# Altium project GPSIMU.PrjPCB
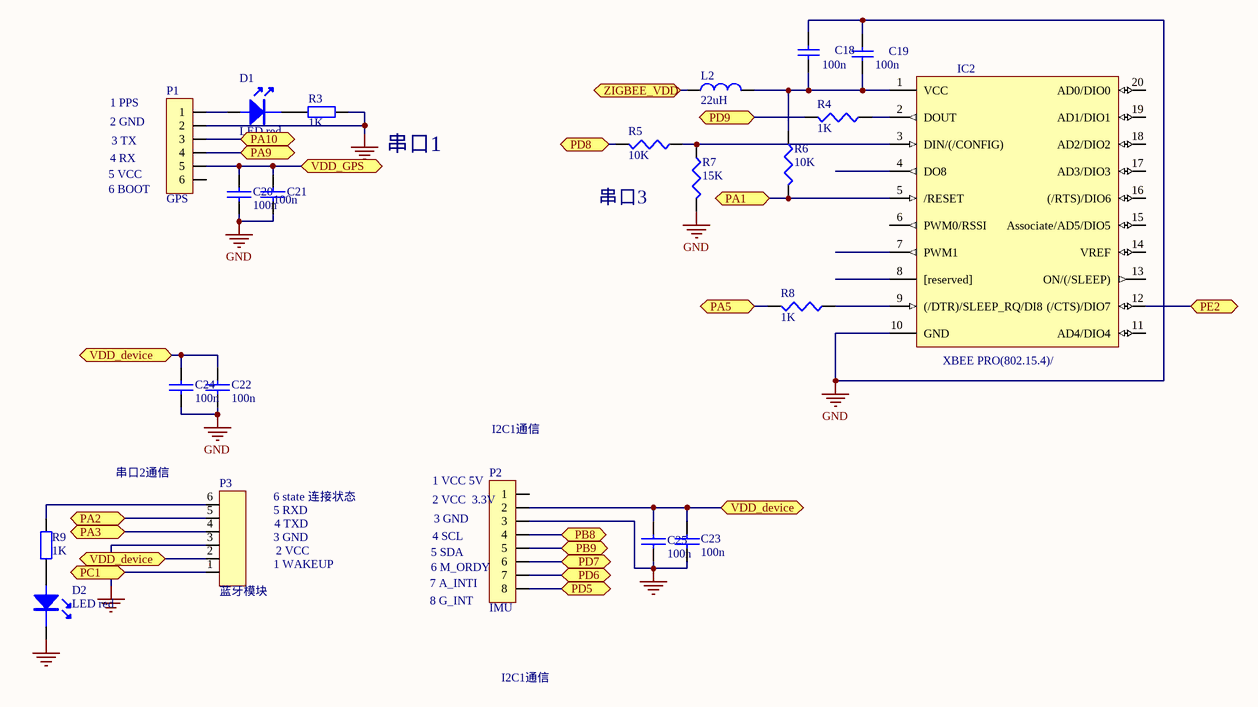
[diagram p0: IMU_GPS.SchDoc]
5 sheets, 107 parts. Net scope: flat (ports and power ports of the same name join across sheets).
Board file: GPSIMU(G).PcbDoc
Sheets:
  IMU_GPS.SchDoc
  IMU_REIO.SchDoc
  CPU_STM32F4.SchDoc
  IMU_POW.SchDoc
  IMU_SD.SchDoc

## Sheet IMU_GPS.SchDoc
size A3

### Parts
C18  100n  [0603]
C19  100n  [0603]
C20  100n  [0603]
C21  100n  [0603]
C22  100n  [0603]
C23  100n  [0603]
C24  100n  [0603]
C25  100n  [0603]
D1  LED red  [D0805]
D2  LED red  [D0805]
IC2  XBEE PRO(802.15.4)/  [SMT-Zigbee-2.0]
L2  22uH  [0603]
P1  GPS  [GPS 28*28MM]
P2  IMU  [GY-85]
P3  蓝牙模块  [HC-06(35.7*15.2MM)]
R3  1K  [0603]
R4  1K  [0603]
R5  10K  [0603]
R6  10K  [0603]
R7  15K  [0603]
R8  1K  [0603]
R9  1K  [0603]

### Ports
PA1, PA2, PA3, PA5, PA9, PA10, PB8, PB9, PC1, PD5, PD6, PD7, PD8, PD9, PE2, VDD_device, VDD_GPS, ZIGBEE_VDD

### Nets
GND: C18.2 C19.2 C20.1 C21.1 C22.1 C23.1 C24.1 C25.1 D2.K IC2.10(GND) P1.2 P2.3 P3.3 R3.1 R7.2
VDD_device: C22.2 C23.2 C24.2 C25.2 P2.2 P3.2 ; port VDD_device
VDD_GPS: C20.2 C21.2 P1.5 ; port VDD_GPS
ZIGBEE_VDD: L2.1 ; port ZIGBEE_VDD
PA1: IC2.5(/RESET) R6.2 ; port PA1
PA2: P3.5 ; port PA2
PA3: P3.4 ; port PA3
PA5: R8.2 ; port PA5
PA9: P1.4 ; port PA9
PA10: P1.3 ; port PA10
PB8: P2.4 ; port PB8
PB9: P2.5 ; port PB9
PC1: P3.1 ; port PC1
PD5: P2.8 ; port PD5
PD6: P2.7 ; port PD6
PD7: P2.6 ; port PD7
PD8: R5.2 ; port PD8
PD9: R4.2 ; port PD9
PE2: IC2.12((/CTS)/DIO7) ; port PE2
NetC18_1: C18.1 C19.1 IC2.1(VCC) L2.2 R6.1
NetD1_A: D1.A P1.1
NetD1_K: D1.K R3.2
NetD2_A: D2.A R9.1
NetIC2_2: IC2.2(DOUT) R4.1
NetIC2_3: IC2.3(DIN/(/CONFIG)) R5.1 R7.1
NetIC2_9: IC2.9((/DTR)/SLEEP_RQ/DI8) R8.1
NetP3_6: P3.6 R9.2

Not connected (* = marked no-connect by the designer): IC2 4(DO8) 6(PWM0/RSSI) 7(PWM1) 8([reserved]) 11(AD4/DIO4) 13(ON/(/SLEEP)) 14(VREF) 15(Associate/AD5/DIO5) 16((/RTS)/DIO6) 17(AD3/DIO3) 18(AD2/DIO2) 19(AD1/DIO1) 20(AD0/DIO0); P1 6; P2 1

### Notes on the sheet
- (near P1) 1 PPS
- (near P1) 2 GND
- (near P1) 6 BOOT
- 5 VCC
- 4 RX
- 3 TX
- 串口1
- (near R5) 串口3
- I2C1通信
- 串口2通信
- 6 state 连接状态
- 5 RXD
- 4 TXD
- (near P2) 1 VCC 5V
- (near P2) 2 VCC  3.3V
- (near P2) 3 GND
- 1 WAKEUP
- 3 GND
- 2 VCC
- (near P2) 7 A_INTI
- (near P2) 6 M_ORDY
- 5 SDA
- (near P2) 4 SCL
- (near P2) 8 G_INT

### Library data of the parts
C18 = Cap: Capacitor
C19 = Cap: Capacitor; Value: 1u
C20-C25 = C-SMD
D1 D2 = diode-LED: LED
IC2 = XBEE PRO(802.15.4)
L2 = L-: Value: 10mH
P1 = CON6-2.54: (栅)围栏式立(卧)6PIN
P2 = CON8-2.54: (栅)围栏式立(卧)8PIN
P3 = CON-SIP6-2.54: 单排针6PIN
R3 R9 = R-0603: 0603(SMD); 功率: 1/10w
R4 R8 = Res3: Resistor; Value: 10K
R5-R7 = Res3: Resistor

## Sheet IMU_REIO.SchDoc
size A4
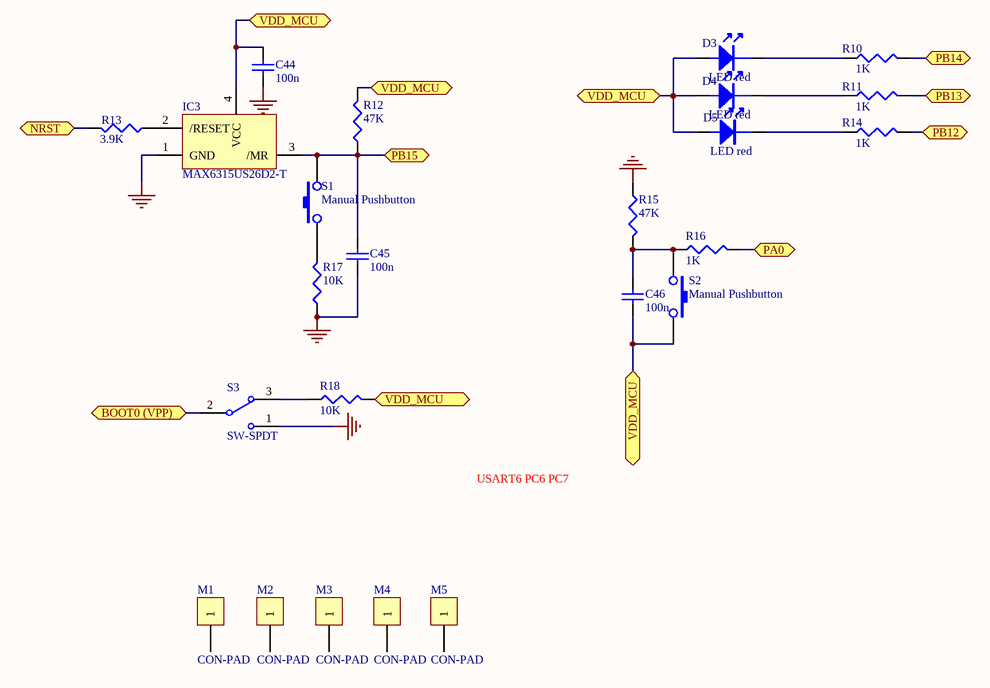
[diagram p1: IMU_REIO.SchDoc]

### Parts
C44  100n  [0603]
C45  100n  [0603]
C46  100n  [0603]
D3  LED red  [D0805]
D4  LED red  [D0805]
D5  LED red  [D0805]
IC3  MAX6315US26D2-T  [TO-253]
M1  CON-PAD  [BAD_MARK]
M2  CON-PAD  [BAD_MARK]
M3  CON-PAD  [BAD_MARK]
M4  CON-PAD  [BAD_MARK]
M5  CON-PAD  [BAD_MARK]
R10  1K  [0603]
R11  1K  [0603]
R12  47K  [0603]
R13  3.9K  [0603]
R14  1K  [0603]
R15  47K  [0603]
R16  1K  [0603]
R17  10K  [0603]
R18  10K  [0603]
S1  Manual Pushbutton  [KEY-6*4]
S2  Manual Pushbutton  [KEY-6*4]
S3  SW-SPDT  [SW-PD-5(10)]

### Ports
BOOT0 (VPP), NRST, PA0, PB12, PB13, PB14, PB15, VDD_MCU

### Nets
GND: C44.2 C45.2 IC3.1(GND) R15.1 R17.1 S3.1
VBAT: C44.1 C46.2 D3.A D4.A D5.A IC3.4(VCC) R12.2 R18.2 S2.2 ; port VDD_MCU
BOOT0 (VPP): S3.2 ; port BOOT0 (VPP)
NRST: R13.2 ; port NRST
PA0: R16.2 ; port PA0
PB12: R14.2 ; port PB12
PB13: R11.2 ; port PB13
PB14: R10.2 ; port PB14
PB15: C45.1 IC3.3(/MR) R12.1 S1.2 ; port PB15
NetC46_1: C46.1 R15.2 R16.1 S2.1
NetD3_K: D3.K R10.1
NetD4_K: D4.K R11.1
NetD5_K: D5.K R14.1
NetIC3_2: IC3.2(/RESET) R13.1
NetR17_2: R17.2 S1.1
NetR18_1: R18.1 S3.3

Not connected (* = marked no-connect by the designer): M1 1; M2 1; M3 1; M4 1; M5 1

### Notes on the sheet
- USART6 PC6 PC7

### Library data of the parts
C44-C46 = Cap: TANTAMOUNT? 595D Vishay Sprague,50V,22.5mOhm
D3-D5 = diode-LED: LED
IC3 = MAX 6468: MAX 6468XS16D3 Reset and Supervisory Circuit
R10-R18 = Res3: Resistor
S1 S2 = 微动开关
S3 = SW-SPDT: SPDT Subminiature Toggle Switch, Right Angle Mounting, Vertical Actuation

## Sheet CPU_STM32F4.SchDoc
size A2
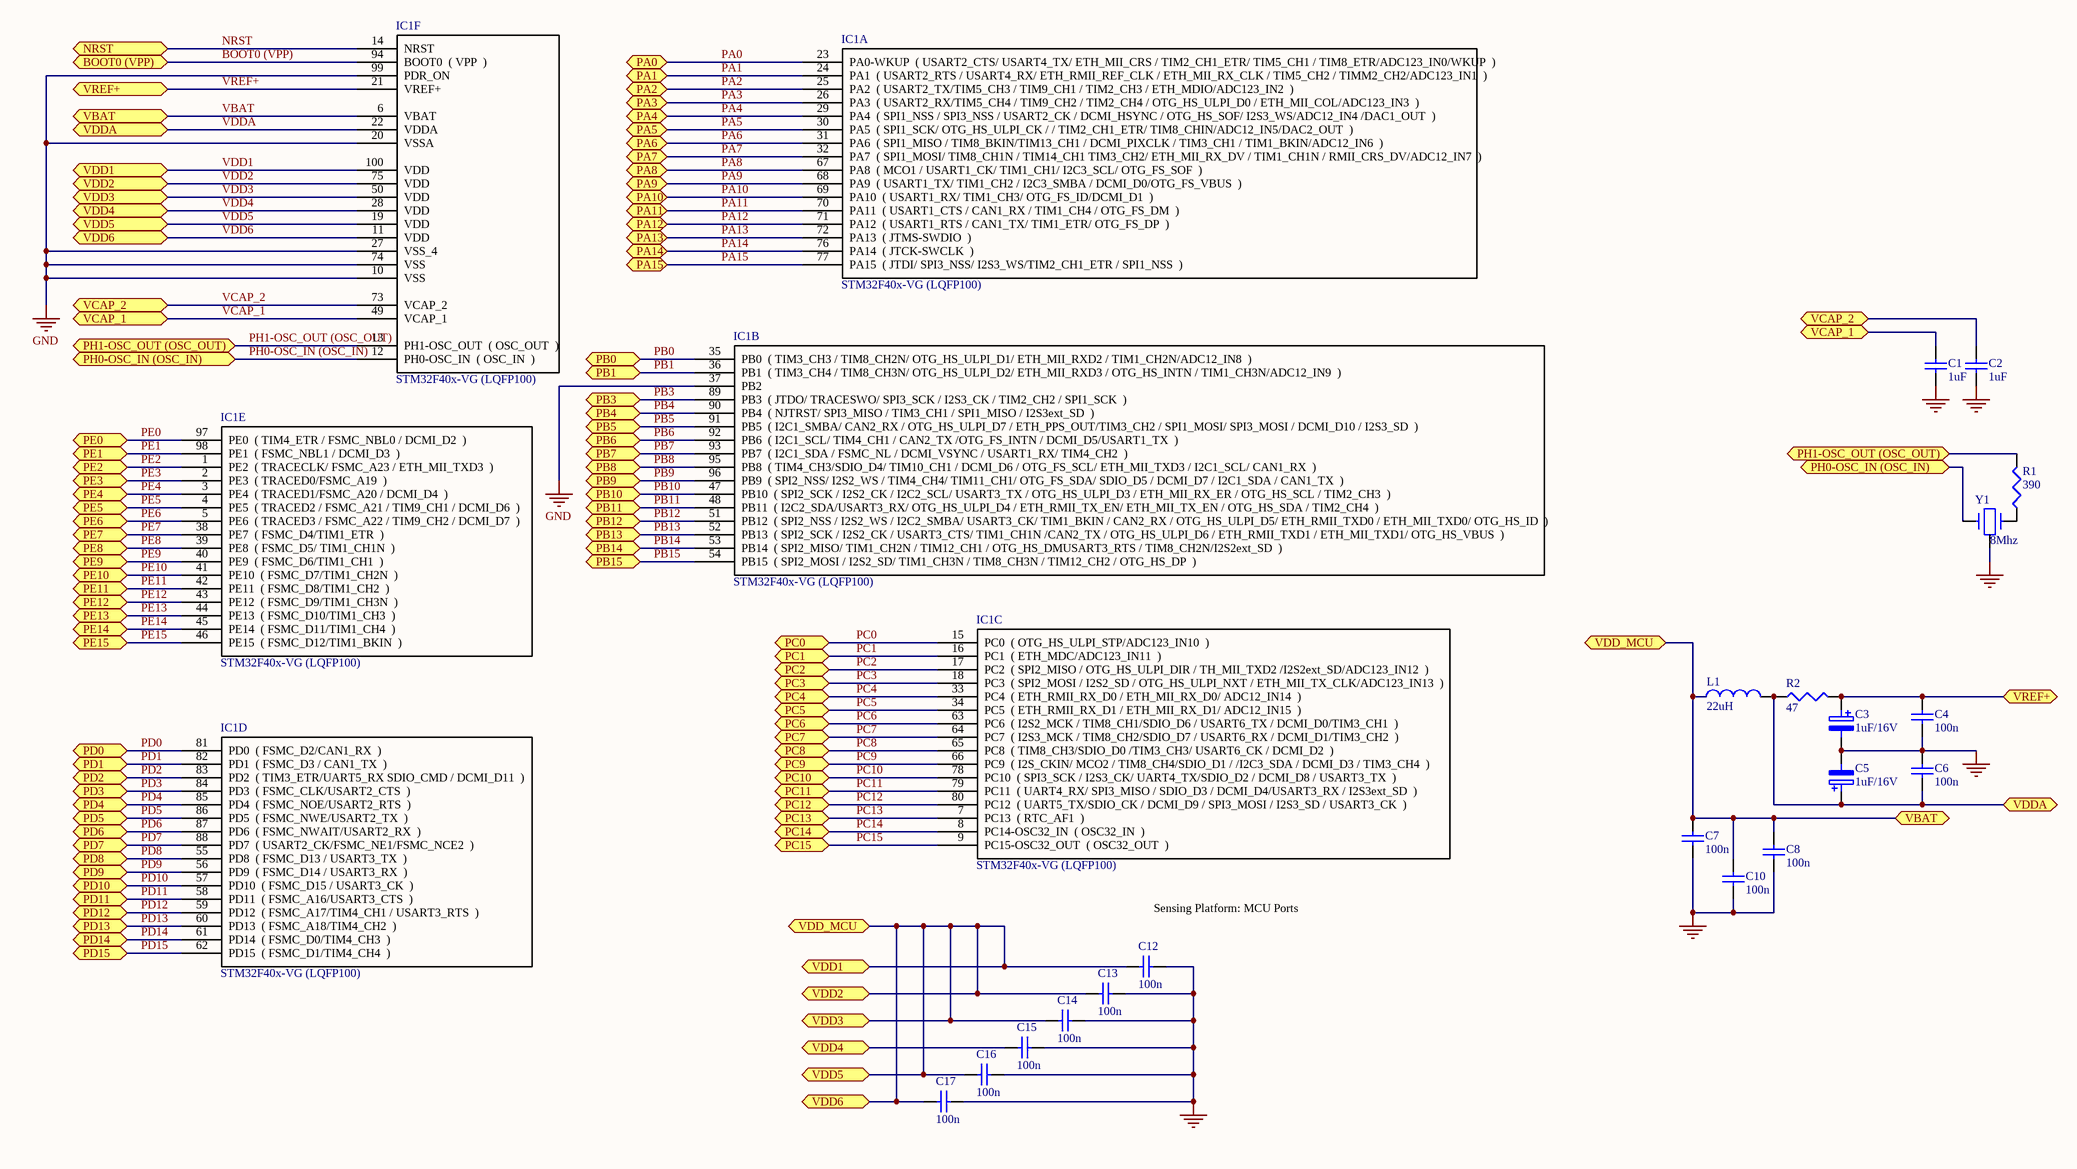
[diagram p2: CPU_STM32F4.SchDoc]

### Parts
C1  1uF  [0603]
C2  1uF  [0603]
C3  1uF/16V  [C-M(0805)]
C4  100n  [0603]
C5  1uF/16V  [C-M(0805)]
C6  100n  [0603]
C7  100n  [0603]
C8  100n  [0603]
C10  100n  [0603]
C12  100n  [0603]
C13  100n  [0603]
C14  100n  [0603]
C15  100n  [0603]
C16  100n  [0603]
C17  100n  [0603]
IC1  STM32F40x-VG (LQFP100)  [LQFP100 (14*14)]  (parts A,B,C,D,E,F of 6)
L1  22uH  [0603]
R1  390  [0603]
R2  47  [0603]
Y1  8Mhz  [XT-3.2*1.5]

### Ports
BOOT0 (VPP), NRST, PA0, PA1, PA2, PA3, PA4, PA5, PA6, PA7, PA8, PA9, PA10, PA11, PA12, PA13, PA14, PA15, PB0, PB1, PB3, PB4, PB5, PB6, PB7, PB8, PB9, PB10, PB11, PB12, PB13, PB14, PB15, PC0, PC1, PC2, PC3, PC4, PC5, PC6, PC7, PC8, PC9, PC10, PC11, PC12, PC13, PC14, PC15, PD0, PD1, PD2, PD3, PD4, PD5, PD6, PD7, PD8, PD9, PD10, PD11, PD12, PD13, PD14, PD15, PE0, PE1, PE2, PE3, PE4, PE5, PE6, PE7, PE8, PE9, PE10, PE11, PE12, PE13, PE14, PE15, PH0-OSC_IN (OSC_IN), PH1-OSC_OUT (OSC_OUT), VBAT, VCAP_1, VCAP_2, VDD1, VDD2, VDD3, VDD4, VDD5, VDD6, VDD_MCU, VDDA, VREF+

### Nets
GND: C1.1 C2.1 C3.2 C4.1 C5.2 C6.2 C7.1 C8.1 C10.1 C12.2 C13.2 C14.2 C15.2 C16.2 C17.2 IC1.10(VSS) IC1.20(VSSA) IC1.27(VSS_4) IC1.37(PB2) IC1.74(VSS) IC1.99(PDR_ON) Y1.2
VBAT: C7.2 C8.2 C10.2 C12.1 C13.1 C14.1 C16.1 C17.1 IC1.6(VBAT) IC1.11(VDD) IC1.19(VDD) IC1.50(VDD) IC1.75(VDD) IC1.100(VDD) L1.1 ; port VBAT, port VDD1, port VDD2, port VDD3, port VDD5, port VDD6, port VDD_MCU  [also labelled VDD1, VDD2, VDD3, VDD5, VDD6]
BOOT0 (VPP): IC1.94(BOOT0__(_VPP__)) ; port BOOT0 (VPP)
NRST: IC1.14(NRST) ; port NRST
PA0: IC1.23(PA0-WKUP__(_USART2_CTS/_USART4_TX/_ETH_MII_CRS_/_TIM2_CH1_ETR/_TIM5_CH1_/_TIM8_ETR/ADC123_IN0/WKUP__)) ; port PA0
PA1: IC1.24(PA1__(_USART2_RTS_/_USART4_RX/_ETH_RMII_REF_CLK_/_ETH_MII_RX_CLK_/_TIM5_CH2_/_TIMM2_CH2/ADC123_IN1__)) ; port PA1
PA2: IC1.25(PA2__(_USART2_TX/TIM5_CH3_/_TIM9_CH1_/_TIM2_CH3_/_ETH_MDIO/ADC123_IN2__)) ; port PA2
PA3: IC1.26(PA3__(_USART2_RX/TIM5_CH4_/_TIM9_CH2_/_TIM2_CH4_/_OTG_HS_ULPI_D0_/_ETH_MII_COL/ADC123_IN3__)) ; port PA3
PA4: IC1.29(PA4__(_SPI1_NSS_/_SPI3_NSS_/_USART2_CK_/_DCMI_HSYNC_/_OTG_HS_SOF/_I2S3_WS/ADC12_IN4_/DAC1_OUT__)) ; port PA4
PA5: IC1.30(PA5__(_SPI1_SCK/_OTG_HS_ULPI_CK_/_/_TIM2_CH1_ETR/_TIM8_CHIN/ADC12_IN5/DAC2_OUT__)) ; port PA5
PA6: IC1.31(PA6__(_SPI1_MISO_/_TIM8_BKIN/TIM13_CH1_/_DCMI_PIXCLK_/_TIM3_CH1_/_TIM1_BKIN/ADC12_IN6__)) ; port PA6
PA7: IC1.32(PA7__(_SPI1_MOSI/_TIM8_CH1N_/_TIM14_CH1_TIM3_CH2/_ETH_MII_RX_DV_/_TIM1_CH1N_/_RMII_CRS_DV/ADC12_IN7__)) ; port PA7
PA8: IC1.67(PA8__(_MCO1_/_USART1_CK/_TIM1_CH1/_I2C3_SCL/_OTG_FS_SOF__)) ; port PA8
PA9: IC1.68(PA9__(_USART1_TX/_TIM1_CH2_/_I2C3_SMBA_/_DCMI_D0/OTG_FS_VBUS__)) ; port PA9
PA10: IC1.69(PA10__(_USART1_RX/_TIM1_CH3/_OTG_FS_ID/DCMI_D1__)) ; port PA10
PA11: IC1.70(PA11__(_USART1_CTS_/_CAN1_RX_/_TIM1_CH4_/_OTG_FS_DM__)) ; port PA11
PA12: IC1.71(PA12__(_USART1_RTS_/_CAN1_TX/_TIM1_ETR/_OTG_FS_DP__)) ; port PA12
PA13: IC1.72(PA13__(_JTMS-SWDIO__)) ; port PA13
PA14: IC1.76(PA14__(_JTCK-SWCLK__)) ; port PA14
PA15: IC1.77(PA15__(_JTDI/_SPI3_NSS/_I2S3_WS/TIM2_CH1_ETR_/_SPI1_NSS__)) ; port PA15
PB0: IC1.35(PB0__(_TIM3_CH3_/_TIM8_CH2N/_OTG_HS_ULPI_D1/_ETH_MII_RXD2_/_TIM1_CH2N/ADC12_IN8__)) ; port PB0
PB1: IC1.36(PB1__(_TIM3_CH4_/_TIM8_CH3N/_OTG_HS_ULPI_D2/_ETH_MII_RXD3_/_OTG_HS_INTN_/_TIM1_CH3N/ADC12_IN9__)) ; port PB1
PB3: IC1.89(PB3__(_JTDO/_TRACESWO/_SPI3_SCK_/_I2S3_CK_/_TIM2_CH2_/_SPI1_SCK__)) ; port PB3
PB4: IC1.90(PB4__(_NJTRST/_SPI3_MISO_/_TIM3_CH1_/_SPI1_MISO_/_I2S3ext_SD__)) ; port PB4
PB5: IC1.91(PB5__(_I2C1_SMBA/_CAN2_RX_/_OTG_HS_ULPI_D7_/_ETH_PPS_OUT/TIM3_CH2_/_SPI1_MOSI/_SPI3_MOSI_/_DCMI_D10_/_I2S3_SD__)) ; port PB5
PB6: IC1.92(PB6__(_I2C1_SCL/_TIM4_CH1_/_CAN2_TX_/OTG_FS_INTN_/_DCMI_D5/USART1_TX__)) ; port PB6
PB7: IC1.93(PB7__(_I2C1_SDA_/_FSMC_NL_/_DCMI_VSYNC_/_USART1_RX/_TIM4_CH2__)) ; port PB7
PB8: IC1.95(PB8__(_TIM4_CH3/SDIO_D4/_TIM10_CH1_/_DCMI_D6_/_OTG_FS_SCL/_ETH_MII_TXD3_/_I2C1_SCL/_CAN1_RX__)) ; port PB8
PB9: IC1.96(PB9__(_SPI2_NSS/_I2S2_WS_/_TIM4_CH4/_TIM11_CH1/_OTG_FS_SDA/_SDIO_D5_/_DCMI_D7_/_I2C1_SDA_/_CAN1_TX__)) ; port PB9
PB10: IC1.47(PB10__(_SPI2_SCK_/_I2S2_CK_/_I2C2_SCL/_USART3_TX_/_OTG_HS_ULPI_D3_/_ETH_MII_RX_ER_/_OTG_HS_SCL_/_TIM2_CH3__)) ; port PB10
PB11: IC1.48(PB11__(_I2C2_SDA/USART3_RX/_OTG_HS_ULPI_D4_/_ETH_RMII_TX_EN/_ETH_MII_TX_EN_/_OTG_HS_SDA_/_TIM2_CH4__)) ; port PB11
PB12: IC1.51(PB12__(_SPI2_NSS_/_I2S2_WS_/_I2C2_SMBA/_USART3_CK/_TIM1_BKIN_/_CAN2_RX_/_OTG_HS_ULPI_D5/_ETH_RMII_TXD0_/_ETH_MII_TXD0/_OTG_HS_ID__)) ; port PB12
PB13: IC1.52(PB13__(_SPI2_SCK_/_I2S2_CK_/_USART3_CTS/_TIM1_CH1N_/CAN2_TX_/_OTG_HS_ULPI_D6_/_ETH_RMII_TXD1_/_ETH_MII_TXD1/_OTG_HS_VBUS__)) ; port PB13
PB14: IC1.53(PB14__(_SPI2_MISO/_TIM1_CH2N_/_TIM12_CH1_/_OTG_HS_DMUSART3_RTS_/_TIM8_CH2N/I2S2ext_SD__)) ; port PB14
PB15: IC1.54(PB15__(_SPI2_MOSI_/_I2S2_SD/_TIM1_CH3N_/_TIM8_CH3N_/_TIM12_CH2_/_OTG_HS_DP__)) ; port PB15
PC0: IC1.15(PC0__(_OTG_HS_ULPI_STP/ADC123_IN10__)) ; port PC0
PC1: IC1.16(PC1__(_ETH_MDC/ADC123_IN11__)) ; port PC1
PC2: IC1.17(PC2__(_SPI2_MISO_/_OTG_HS_ULPI_DIR_/_TH_MII_TXD2_/I2S2ext_SD/ADC123_IN12__)) ; port PC2
PC3: IC1.18(PC3__(_SPI2_MOSI_/_I2S2_SD_/_OTG_HS_ULPI_NXT_/_ETH_MII_TX_CLK/ADC123_IN13__)) ; port PC3
PC4: IC1.33(PC4__(_ETH_RMII_RX_D0_/_ETH_MII_RX_D0/_ADC12_IN14__)) ; port PC4
PC5: IC1.34(PC5__(_ETH_RMII_RX_D1_/_ETH_MII_RX_D1/_ADC12_IN15__)) ; port PC5
PC6: IC1.63(PC6__(_I2S2_MCK_/_TIM8_CH1/SDIO_D6_/_USART6_TX_/_DCMI_D0/TIM3_CH1__)) ; port PC6
PC7: IC1.64(PC7__(_I2S3_MCK_/_TIM8_CH2/SDIO_D7_/_USART6_RX_/_DCMI_D1/TIM3_CH2__)) ; port PC7
PC8: IC1.65(PC8__(_TIM8_CH3/SDIO_D0_/TIM3_CH3/_USART6_CK_/_DCMI_D2__)) ; port PC8
PC9: IC1.66(PC9__(_I2S_CKIN/_MCO2_/_TIM8_CH4/SDIO_D1_/_/I2C3_SDA_/_DCMI_D3_/_TIM3_CH4__)) ; port PC9
PC10: IC1.78(PC10__(_SPI3_SCK_/_I2S3_CK/_UART4_TX/SDIO_D2_/_DCMI_D8_/_USART3_TX__)) ; port PC10
PC11: IC1.79(PC11__(_UART4_RX/_SPI3_MISO_/_SDIO_D3_/_DCMI_D4/USART3_RX_/_I2S3ext_SD__)) ; port PC11
PC12: IC1.80(PC12__(_UART5_TX/SDIO_CK_/_DCMI_D9_/_SPI3_MOSI_/_I2S3_SD_/_USART3_CK__)) ; port PC12
PC13: IC1.7(PC13__(_RTC_AF1__)) ; port PC13
PC14: IC1.8(PC14-OSC32_IN__(_OSC32_IN__)) ; port PC14
PC15: IC1.9(PC15-OSC32_OUT__(_OSC32_OUT__)) ; port PC15
PD0: IC1.81(PD0__(_FSMC_D2/CAN1_RX__)) ; port PD0
PD1: IC1.82(PD1__(_FSMC_D3_/_CAN1_TX__)) ; port PD1
PD2: IC1.83(PD2__(_TIM3_ETR/UART5_RX_SDIO_CMD_/_DCMI_D11__)) ; port PD2
PD3: IC1.84(PD3__(_FSMC_CLK/USART2_CTS__)) ; port PD3
PD4: IC1.85(PD4__(_FSMC_NOE/USART2_RTS__)) ; port PD4
PD5: IC1.86(PD5__(_FSMC_NWE/USART2_TX__)) ; port PD5
PD6: IC1.87(PD6__(_FSMC_NWAIT/USART2_RX__)) ; port PD6
PD7: IC1.88(PD7__(_USART2_CK/FSMC_NE1/FSMC_NCE2__)) ; port PD7
PD8: IC1.55(PD8__(_FSMC_D13_/_USART3_TX__)) ; port PD8
PD9: IC1.56(PD9__(_FSMC_D14_/_USART3_RX__)) ; port PD9
PD10: IC1.57(PD10__(_FSMC_D15_/_USART3_CK__)) ; port PD10
PD11: IC1.58(PD11__(_FSMC_A16/USART3_CTS__)) ; port PD11
PD12: IC1.59(PD12__(_FSMC_A17/TIM4_CH1_/_USART3_RTS__)) ; port PD12
PD13: IC1.60(PD13__(_FSMC_A18/TIM4_CH2__)) ; port PD13
PD14: IC1.61(PD14__(_FSMC_D0/TIM4_CH3__)) ; port PD14
PD15: IC1.62(PD15__(_FSMC_D1/TIM4_CH4__)) ; port PD15
PE0: IC1.97(PE0__(_TIM4_ETR_/_FSMC_NBL0_/_DCMI_D2__)) ; port PE0
PE1: IC1.98(PE1__(_FSMC_NBL1_/_DCMI_D3__)) ; port PE1
PE2: IC1.1(PE2__(_TRACECLK/_FSMC_A23_/_ETH_MII_TXD3__)) ; port PE2
PE3: IC1.2(PE3__(_TRACED0/FSMC_A19__)) ; port PE3
PE4: IC1.3(PE4__(_TRACED1/FSMC_A20_/_DCMI_D4__)) ; port PE4
PE5: IC1.4(PE5__(_TRACED2_/_FSMC_A21_/_TIM9_CH1_/_DCMI_D6__)) ; port PE5
PE6: IC1.5(PE6__(_TRACED3_/_FSMC_A22_/_TIM9_CH2_/_DCMI_D7__)) ; port PE6
PE7: IC1.38(PE7__(_FSMC_D4/TIM1_ETR__)) ; port PE7
PE8: IC1.39(PE8__(_FSMC_D5/_TIM1_CH1N__)) ; port PE8
PE9: IC1.40(PE9__(_FSMC_D6/TIM1_CH1__)) ; port PE9
PE10: IC1.41(PE10__(_FSMC_D7/TIM1_CH2N__)) ; port PE10
PE11: IC1.42(PE11__(_FSMC_D8/TIM1_CH2__)) ; port PE11
PE12: IC1.43(PE12__(_FSMC_D9/TIM1_CH3N__)) ; port PE12
PE13: IC1.44(PE13__(_FSMC_D10/TIM1_CH3__)) ; port PE13
PE14: IC1.45(PE14__(_FSMC_D11/TIM1_CH4__)) ; port PE14
PE15: IC1.46(PE15__(_FSMC_D12/TIM1_BKIN__)) ; port PE15
PH0-OSC_IN (OSC_IN): IC1.12(PH0-OSC_IN__(_OSC_IN__)) Y1.1 ; port PH0-OSC_IN (OSC_IN)
PH1-OSC_OUT (OSC_OUT): IC1.13(PH1-OSC_OUT__(_OSC_OUT__)) R1.2 ; port PH1-OSC_OUT (OSC_OUT)
VCAP_1: C1.2 IC1.49(VCAP_1) ; port VCAP_1
VCAP_2: C2.2 IC1.73(VCAP_2) ; port VCAP_2
VDD4: C15.1 IC1.28(VDD) ; port VDD4
VDDA: C5.1 C6.1 IC1.22(VDDA) L1.2 R2.1 ; port VDDA
VREF+: C3.1 C4.2 IC1.21(VREF+) R2.2 ; port VREF+
NetR1_1: R1.1 Y1.3

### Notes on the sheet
- (near C12) Sensing Platform: MCU Ports

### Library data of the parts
C1 C2 = Cap: TANTAMOUNT? 595D Vishay Sprague,50V,22.5mOhm; Value: 1u
C3 C5 = C-A(3216-18): 耐压: 10V
C4 C6-C8 C10 C13-C17 = Cap: as C44 on sheet IMU_REIO
C12 = Cap: TANTAMOUNT? 595D Vishay Sprague,50V,22.5mOhm; Value: 4.7u
IC1 = STM32F40x-VG
L1 = Inductor: fcm1608-0603; Code_IEC: 1005
R1 R2 = Res3: Resistor
Y1 = CRYSTAL-X3: 3PIN; 频率: 20MHZ-39.9MHZ

## Sheet IMU_POW.SchDoc
size A3
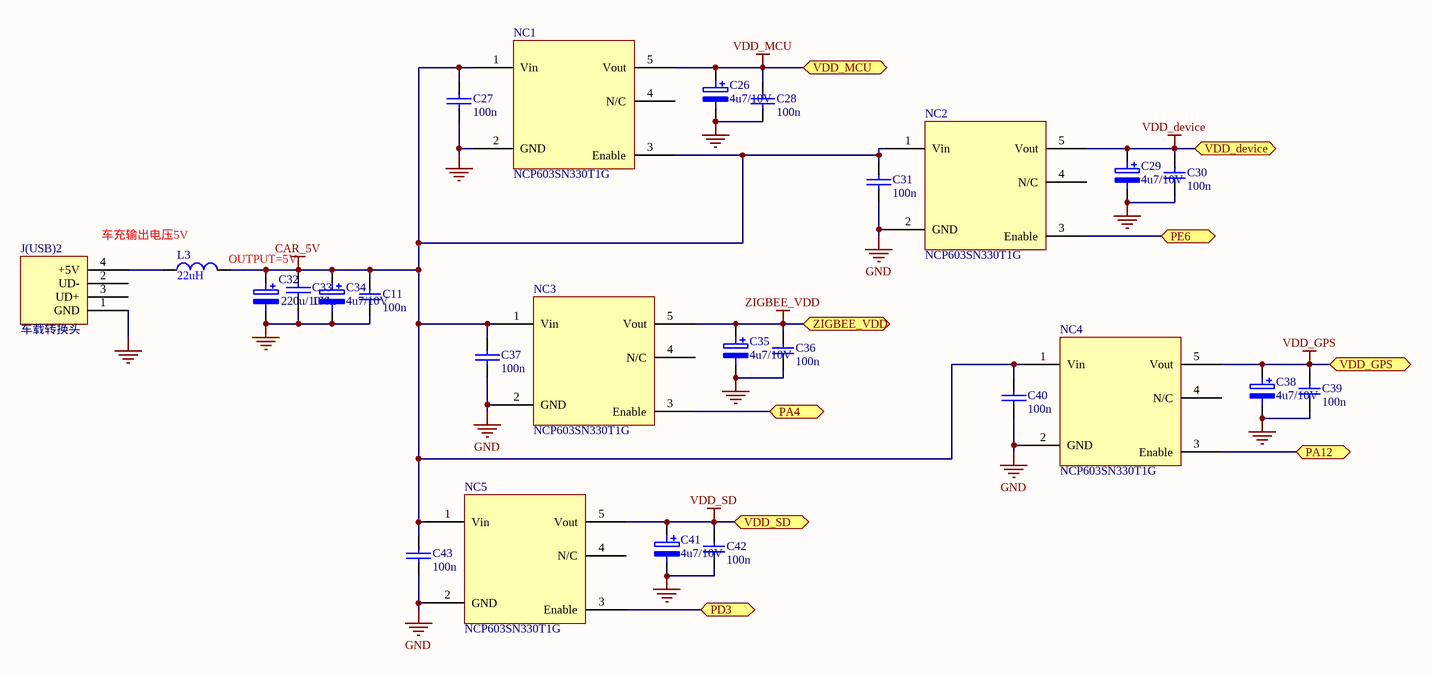
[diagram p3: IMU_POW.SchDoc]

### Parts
C11  100n  [0603]
C26  4u7/10V  [C-A(3216-18)]
C27  100n  [0603]
C28  100n  [0603]
C29  4u7/10V  [C-A(3216-18)]
C30  100n  [0603]
C31  100n  [0603]
C32  220u/10V  [C-C(6032-28)]
C33  100n  [0603]
C34  4u7/10V  [C-A(3216-18)]
C35  4u7/10V  [C-A(3216-18)]
C36  100n  [0603]
C37  100n  [0603]
C38  4u7/10V  [C-A(3216-18)]
C39  100n  [0603]
C40  100n  [0603]
C41  4u7/10V  [C-A(3216-18)]
C42  100n  [0603]
C43  100n  [0603]
J(USB)2  车载转换头  [SMT-USB]
L3  22uH  [0603]
NC1  NCP603SN330T1G  [TSSOP-5]
NC2  NCP603SN330T1G  [TSSOP-5]
NC3  NCP603SN330T1G  [TSSOP-5]
NC4  NCP603SN330T1G  [TSSOP-5]
NC5  NCP603SN330T1G  [TSSOP-5]

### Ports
PA4, PA12, PD3, PE6, VDD_device, VDD_GPS, VDD_MCU, VDD_SD, ZIGBEE_VDD

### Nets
CAR_5V: C11.2 C27.2 C31.2 C32.1 C33.2 C34.1 C37.2 C40.2 C43.2 L3.2 NC1.1(Vin) NC1.3(Enable) NC2.1(Vin) NC3.1(Vin) NC4.1(Vin) NC5.1(Vin)
GND: C11.1 C26.2 C27.1 C28.1 C29.2 C30.1 C31.1 C32.2 C33.1 C34.2 C35.2 C36.1 C37.1 C38.2 C39.1 C40.1 C41.2 C42.1 C43.1 J(USB)2.1(GND) NC1.2(GND) NC2.2(GND) NC3.2(GND) NC4.2(GND) NC5.2(GND)
VDD_device: C29.1 C30.2 NC2.5(Vout) ; port VDD_device
VDD_GPS: C38.1 C39.2 NC4.5(Vout) ; port VDD_GPS
VDD_MCU: C26.1 C28.2 NC1.5(Vout) ; port VDD_MCU  [project net VBAT]
VDD_SD: C41.1 C42.2 NC5.5(Vout) ; port VDD_SD
ZIGBEE_VDD: C35.1 C36.2 NC3.5(Vout) ; port ZIGBEE_VDD
PA4: NC3.3(Enable) ; port PA4
PA12: NC4.3(Enable) ; port PA12
PD3: NC5.3(Enable) ; port PD3
PE6: NC2.3(Enable) ; port PE6
NetJ(USB)2_4: J(USB)2.4(+5V) L3.1

Not connected (* = marked no-connect by the designer): J(USB)2 2(UD-) 3(UD+); NC1 4(N/C); NC2 4(N/C); NC3 4(N/C); NC4 4(N/C); NC5 4(N/C)

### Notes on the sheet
- 车充输出电压5V
- OUTPUT=5V

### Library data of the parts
C11 = Cap: as C44 on sheet IMU_REIO
C26 C29 C34 C35 C38 C41 = C-A(3216-18): 耐压: 10V
C27 = C
C28 C31 C37 C40 C43 = C-SMD
C30 C36 C39 C42 = Cap Semi: Capacitor (Semiconductor SIM Model); Value: 100nF
C32 = C-RB.1
C33 = C-SMD电容
J(USB)2 = CON-USB1: USB
L3 = INDUCTOR
NC1-NC5 = NCP551

## Sheet IMU_SD.SchDoc
size A4
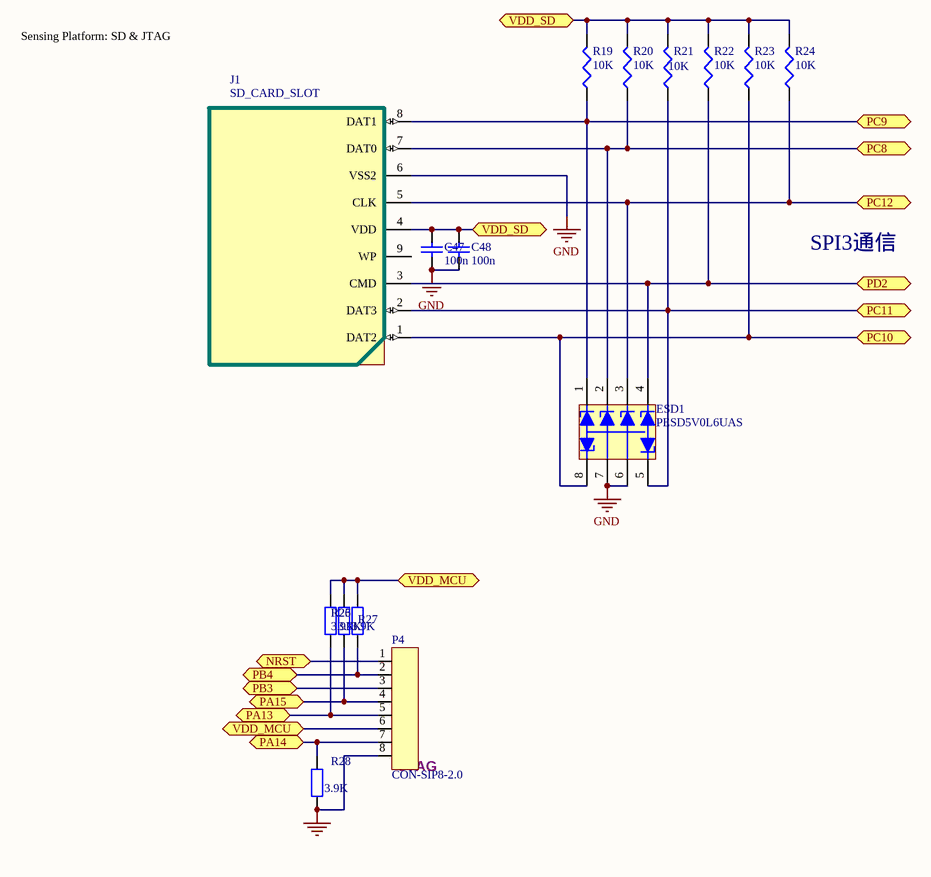
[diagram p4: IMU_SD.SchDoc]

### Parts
C47  100n  [0603]
C48  100n  [0603]
ESD1  PESD5V0L6UAS  [MSOP-8]
J1  SD_CARD_SLOT  [mini-SD]
P4  CON-SIP8-2.0  [PLUG1.27-8P]
R19  10K  [0603]
R20  10K  [0603]
R21  10K  [0603]
R22  10K  [0603]
R23  10K  [0603]
R24  10K  [0603]
R25  3.9K  [0603]
R26  3.9K  [0603]
R27  3.9K  [0603]
R28  3.9K  [0603]

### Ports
NRST, PA13, PA14, PA15, PB3, PB4, PC8, PC9, PC10, PC11, PC12, PD2, VDD_MCU, VDD_SD

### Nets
GND: C47.2 C48.2 ESD1.6 ESD1.7 J1.6(VSS2) P4.8 R28.1
VBAT: P4.6 R25.2 R26.2 R27.2 ; port VDD_MCU
VDD_SD: C47.1 C48.1 J1.4(VDD) R19.2 R20.2 R21.2 R22.2 R23.2 R24.2 ; port VDD_SD
NRST: P4.1 ; port NRST
PA13: P4.5 R25.1 ; port PA13
PA14: P4.7 R28.2 ; port PA14
PA15: P4.4 R26.1 ; port PA15
PB3: P4.3 ; port PB3
PB4: P4.2 R27.1 ; port PB4
PC8: ESD1.2 J1.7(DAT0) R20.1 ; port PC8
PC9: ESD1.1 J1.8(DAT1) R19.1 ; port PC9
PC10: ESD1.8 J1.1(DAT2) R23.1 ; port PC10
PC11: ESD1.5 J1.2(DAT3) R21.1 ; port PC11
PC12: ESD1.3 J1.5(CLK) R24.1 ; port PC12
PD2: ESD1.4 J1.3(CMD) R22.1 ; port PD2

Not connected (* = marked no-connect by the designer): J1 9(WP)

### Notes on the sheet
- Sensing Platform: SD & JTAG
- SPI3通信
- (near P4) JTAG

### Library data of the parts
C47 C48 = Cap: Capacitor
ESD1 = PESD5V0L6U
P4 = CON-SIP8-2.0: 单排针8PIN
R19-R24 = Res3: Resistor
R25-R28 = R-0805: 0805(SMD); 功率: 1/8w

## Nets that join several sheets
GND: IMU_GPS (15 pins), IMU_REIO (6 pins), CPU_STM32F4 (22 pins), IMU_POW (25 pins), IMU_SD (7 pins)
VBAT: IMU_REIO (9 pins), CPU_STM32F4 (15 pins), IMU_POW (C26.1 C28.2 NC1.5), IMU_SD (P4.6 R25.2 R26.2 R27.2)
VDD_device: IMU_GPS (6 pins), IMU_POW (C29.1 C30.2 NC2.5)
VDD_GPS: IMU_GPS (C20.2 C21.2 P1.5), IMU_POW (C38.1 C39.2 NC4.5)
VDD_SD: IMU_POW (C41.1 C42.2 NC5.5), IMU_SD (9 pins)
ZIGBEE_VDD: IMU_GPS (L2.1), IMU_POW (C35.1 C36.2 NC3.5)
BOOT0 (VPP): IMU_REIO (S3.2), CPU_STM32F4 (IC1.94)
NRST: IMU_REIO (R13.2), CPU_STM32F4 (IC1.14), IMU_SD (P4.1)
PA0: IMU_REIO (R16.2), CPU_STM32F4 (IC1.23)
PA1: IMU_GPS (IC2.5 R6.2), CPU_STM32F4 (IC1.24)
PA2: IMU_GPS (P3.5), CPU_STM32F4 (IC1.25)
PA3: IMU_GPS (P3.4), CPU_STM32F4 (IC1.26)
PA4: CPU_STM32F4 (IC1.29), IMU_POW (NC3.3)
PA5: IMU_GPS (R8.2), CPU_STM32F4 (IC1.30)
PA9: IMU_GPS (P1.4), CPU_STM32F4 (IC1.68)
PA10: IMU_GPS (P1.3), CPU_STM32F4 (IC1.69)
PA12: CPU_STM32F4 (IC1.71), IMU_POW (NC4.3)
PA13: CPU_STM32F4 (IC1.72), IMU_SD (P4.5 R25.1)
PA14: CPU_STM32F4 (IC1.76), IMU_SD (P4.7 R28.2)
PA15: CPU_STM32F4 (IC1.77), IMU_SD (P4.4 R26.1)
PB3: CPU_STM32F4 (IC1.89), IMU_SD (P4.3)
PB4: CPU_STM32F4 (IC1.90), IMU_SD (P4.2 R27.1)
PB8: IMU_GPS (P2.4), CPU_STM32F4 (IC1.95)
PB9: IMU_GPS (P2.5), CPU_STM32F4 (IC1.96)
PB12: IMU_REIO (R14.2), CPU_STM32F4 (IC1.51)
PB13: IMU_REIO (R11.2), CPU_STM32F4 (IC1.52)
PB14: IMU_REIO (R10.2), CPU_STM32F4 (IC1.53)
PB15: IMU_REIO (C45.1 IC3.3 R12.1 S1.2), CPU_STM32F4 (IC1.54)
PC1: IMU_GPS (P3.1), CPU_STM32F4 (IC1.16)
PC8: CPU_STM32F4 (IC1.65), IMU_SD (ESD1.2 J1.7 R20.1)
PC9: CPU_STM32F4 (IC1.66), IMU_SD (ESD1.1 J1.8 R19.1)
PC10: CPU_STM32F4 (IC1.78), IMU_SD (ESD1.8 J1.1 R23.1)
PC11: CPU_STM32F4 (IC1.79), IMU_SD (ESD1.5 J1.2 R21.1)
PC12: CPU_STM32F4 (IC1.80), IMU_SD (ESD1.3 J1.5 R24.1)
PD2: CPU_STM32F4 (IC1.83), IMU_SD (ESD1.4 J1.3 R22.1)
PD3: CPU_STM32F4 (IC1.84), IMU_POW (NC5.3)
PD5: IMU_GPS (P2.8), CPU_STM32F4 (IC1.86)
PD6: IMU_GPS (P2.7), CPU_STM32F4 (IC1.87)
PD7: IMU_GPS (P2.6), CPU_STM32F4 (IC1.88)
PD8: IMU_GPS (R5.2), CPU_STM32F4 (IC1.55)
PD9: IMU_GPS (R4.2), CPU_STM32F4 (IC1.56)
PE2: IMU_GPS (IC2.12), CPU_STM32F4 (IC1.1)
PE6: CPU_STM32F4 (IC1.5), IMU_POW (NC2.3)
